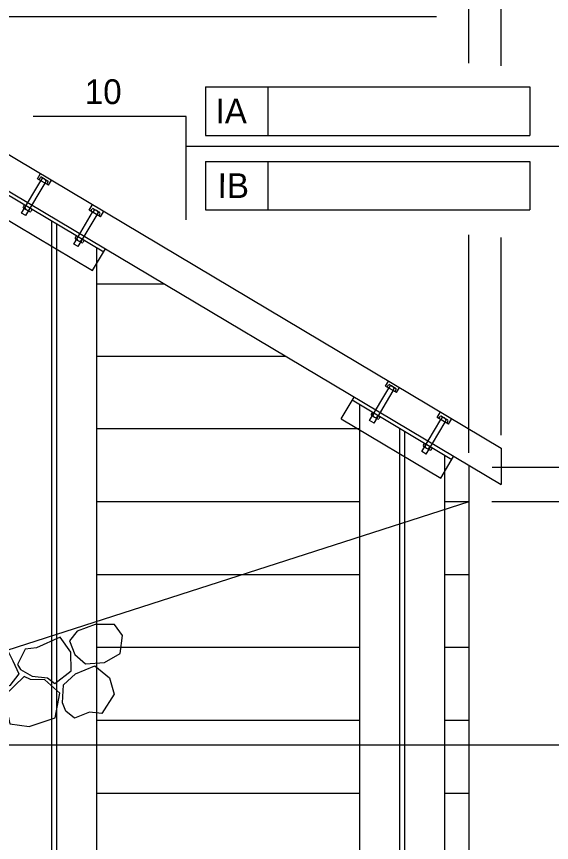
# Model space of a CAD drawing. Extents: x 638304 to 640306, y 296653 to 298435.
# Drawn here: x 639709.6 to 639774.4, y 297344.2 to 297444.4 of the extents above; entities that cross this region are included whole.
import ezdxf

# ---------------------------------------------------------------- set-up
doc = ezdxf.new("R2010")
doc.units = 0
for name, color, linetype in [('4', 7, 'Continuous'), ('Level 3', 7, 'Continuous'), ('Level 4', 7, 'Continuous'), ('Level 8', 7, 'Continuous')]:
    doc.layers.add(name, color=color, linetype=linetype)

# ---------------------------------------------------------------- blocks, each defined once
blk = doc.blocks.new('ROCK')
at = {"layer": '4'}
for points in [[(2.36725, 1.088), (2.2065, 0.82625), (2.378625, 0.506625), (2.66975, 0.3095), (3.128875, 0.403375), (3.48475, 0.6775), (3.4915, 1.123375), (3.25625, 1.36725), (2.783625, 1.308375)], [(1.10175, -0.02725), (1.4015, -0.159125), (1.78825, -0.148875), (1.980875, -0.266), (2.343375, 0.09475), (2.27875, 0.5505), (1.969375, 0.883), (1.4225, 0.553625), (1.152875, 0.479), (1.0105, 0.082)], [(0.74675, 0.359875), (0.882, 0.16), (1.072875, -0.144), (0.892, -0.457375), (0.448125, -0.758625), (0.1, -0.49325), (-0.095, -0.146375), (0.202875, 0.1025), (0.579125, 0.219875)], [(2.231375, -0.71725), (2.2025, -0.266375), (2.45475, 0.037125), (2.9085, 0.28875), (3.2995, 0.047625), (3.46875, -0.344), (3.231625, -0.855), (2.92, -0.860375), (2.5765, -1.054625), (2.340375, -0.904375)], [(1.2085, -0.192875), (0.778375, -0.737625), (1.008375, -1.391375), (1.48725, -1.396875), (2.09825, -1.106625), (2.133375, -0.486375), (1.723125, -0.203375), (1.37425, -0.239875)]]:
    blk.add_lwpolyline(points, close=True, dxfattribs=at)

msp = doc.modelspace()

# ---------------------------------------------------------------- linework, layer by layer
at = {"layer": 'Level 3'}
for p, q in [((639680.52, 297444.35), (639768.27, 297392.03)), ((639680.52, 297439.93), (639768.27, 297387.61)), ((639712.08, 297424.7), (639712.44, 297425.32)), ((639710.17, 297420.53), (639712.49, 297424.46)), ((639713.43, 297423.91), (639712.08, 297424.7)), ((639712.28, 297424.58), (639712.44, 297424.85)), ((639712.66, 297424.72), (639712.51, 297424.45)), ((639712.6, 297424.87), (639713.32, 297424.45)), ((639713.14, 297424.44), (639712.98, 297424.17)), ((639713.23, 297424.02), (639713.38, 297424.3)), ((639713.43, 297423.91), (639713.79, 297424.52)), ((639710.7, 297420.22), (639713.02, 297424.15)), ((639710.5, 297421.56), (639710.34, 297421.29)), ((639710.56, 297421.16), (639710.72, 297421.43)), ((639718.37, 297420.88), (639718.73, 297421.5)), ((639706.7, 297420.75), (639718.78, 297413.55)), ((639710.7, 297420.22), (639710.17, 297420.53)), ((639710.4, 297421.14), (639711.12, 297420.72)), ((639711.04, 297420.88), (639711.19, 297421.15)), ((639711.44, 297421.01), (639711.28, 297420.74)), ((639716.49, 297416.77), (639718.78, 297420.64)), ((639717.02, 297416.46), (639719.31, 297420.33)), ((639719.72, 297420.09), (639718.37, 297420.88)), ((639718.57, 297420.76), (639718.73, 297421.03)), ((639718.95, 297420.9), (639718.79, 297420.63)), ((639718.89, 297421.06), (639719.61, 297420.63)), ((639719.43, 297420.62), (639719.27, 297420.35)), ((639719.52, 297420.21), (639719.67, 297420.48)), ((639719.72, 297420.09), (639720.08, 297420.7)), ((639716.81, 297417.8), (639716.65, 297417.53)), ((639716.71, 297417.38), (639717.44, 297416.96)), ((639716.88, 297417.39), (639717.04, 297417.66)), ((639717.36, 297417.12), (639717.52, 297417.38)), ((639717.76, 297417.24), (639717.6, 297416.97)), ((639717.02, 297416.46), (639716.49, 297416.77)), ((639718.78, 297413.55), (639720.35, 297416.18)), ((639719.25, 297414.35), (639719.25, 297371.02)), ((639727.5, 297411.92), (639719.25, 297411.92)), ((639719.25, 297405.66), (639719.25, 297400.99)), ((639742.22, 297403.15), (639719.25, 297403.15)), ((639752.35, 297395.38), (639754.67, 297399.31)), ((639754.26, 297399.55), (639754.62, 297400.17)), ((639755.61, 297398.76), (639754.26, 297399.55)), ((639754.46, 297399.43), (639754.62, 297399.7)), ((639754.84, 297399.57), (639754.69, 297399.3)), ((639754.78, 297399.72), (639755.5, 297399.3)), ((639755.32, 297399.29), (639755.16, 297399.02)), ((639755.61, 297398.76), (639755.97, 297399.37)), ((639748.88, 297395.6), (639750.46, 297398.23)), ((639752.88, 297395.07), (639755.2, 297399)), ((639755.41, 297398.87), (639755.56, 297399.15)), ((639752.68, 297396.41), (639752.52, 297396.14)), ((639752.74, 297396.01), (639752.9, 297396.28)), ((639760.55, 297395.73), (639760.91, 297396.35)), ((639748.88, 297395.6), (639760.96, 297388.4)), ((639752.88, 297395.07), (639752.35, 297395.38)), ((639752.58, 297395.99), (639753.29, 297395.57)), ((639753.22, 297395.73), (639753.37, 297396)), ((639753.62, 297395.86), (639753.46, 297395.59)), ((639758.67, 297391.62), (639760.96, 297395.49)), ((639761.9, 297394.94), (639760.55, 297395.73)), ((639760.75, 297395.61), (639760.91, 297395.88)), ((639761.13, 297395.75), (639760.97, 297395.48)), ((639761.07, 297395.91), (639761.79, 297395.48)), ((639761.61, 297395.47), (639761.45, 297395.2)), ((639761.7, 297395.06), (639761.85, 297395.33)), ((639761.9, 297394.94), (639762.26, 297395.55)), ((639751.12, 297394.37), (639719.25, 297394.37)), ((639751.12, 297394.26), (639751.12, 297381.26)), ((639759.2, 297391.31), (639761.49, 297395.18)), ((639758.99, 297392.65), (639758.83, 297392.38)), ((639758.89, 297392.23), (639759.62, 297391.81)), ((639759.06, 297392.24), (639759.22, 297392.51)), ((639759.54, 297391.97), (639759.7, 297392.23)), ((639759.2, 297391.31), (639758.67, 297391.62)), ((639759.94, 297392.09), (639759.78, 297391.82)), ((639768.27, 297392.03), (639768.27, 297387.61)), ((639760.96, 297388.4), (639762.53, 297391.03)), ((639761.43, 297389.2), (639761.43, 297384.63)), ((639764.38, 297389.93), (639764.38, 297385.53)), ((639764.38, 297385.53), (639673.75, 297356.36)), ((639751.12, 297385.53), (639719.25, 297385.53)), ((639764.38, 297385.53), (639761.43, 297385.53)), ((639764.38, 297385.53), (639764.38, 297323.64)), ((639761.43, 297384.7), (639761.43, 297312.21)), ((639751.12, 297381.26), (639751.12, 297311.93)), ((639736.91, 297376.69), (639719.25, 297376.69)), ((639751.12, 297376.69), (639736.91, 297376.69)), ((639764.38, 297376.69), (639761.43, 297376.69)), ((639719.25, 297371.02), (639719.25, 297312.21)), ((639751.12, 297367.85), (639719.25, 297367.85)), ((639764.38, 297367.85), (639761.43, 297367.85)), ((639751.12, 297359.01), (639719.25, 297359.01)), ((639764.38, 297359.01), (639761.43, 297359.01)), ((639751.12, 297350.17), (639719.25, 297350.17)), ((639764.38, 297350.17), (639761.43, 297350.17))]:
    msp.add_line(p, q, dxfattribs=at)
for centre, radius, start, end in [((639712.53, 297424.75), 0.139, 346.8498, 131.9461), ((639712.73, 297424.29), 0.438, 20.448, 98.348), ((639713.23, 297424.32), 0.153, 61.225, 128.111), ((639713.23, 297424.32), 0.153, 350.6849, 61.225), ((639710.47, 297421.26), 0.139, 166.9183, 312.0147), ((639710.97, 297421.31), 0.438, 200.5165, 278.4165), ((639711.19, 297420.85), 0.153, 170.7534, 237.6394), ((639711.19, 297420.85), 0.153, 237.6394, 308.1795), ((639718.82, 297420.93), 0.139, 346.8498, 131.9461), ((639719.02, 297420.47), 0.438, 20.448, 98.348), ((639719.52, 297420.5), 0.153, 61.225, 128.111), ((639719.52, 297420.5), 0.153, 350.6849, 61.225), ((639716.79, 297417.49), 0.139, 166.9183, 312.0147), ((639717.29, 297417.54), 0.438, 200.5165, 278.4165), ((639717.51, 297417.09), 0.153, 170.7534, 237.6394), ((639717.51, 297417.09), 0.153, 237.6394, 308.1795), ((639754.71, 297399.6), 0.139, 346.8498, 131.9461), ((639754.91, 297399.14), 0.438, 20.448, 98.348), ((639755.41, 297399.17), 0.153, 61.225, 128.111), ((639755.41, 297399.17), 0.153, 350.6849, 61.225), ((639752.65, 297396.11), 0.139, 166.9183, 312.0147), ((639753.15, 297396.16), 0.438, 200.5165, 278.4165), ((639753.37, 297395.7), 0.153, 170.7534, 237.6394), ((639753.37, 297395.7), 0.153, 237.6394, 308.1795), ((639761, 297395.78), 0.139, 346.8498, 131.9461), ((639761.2, 297395.32), 0.438, 20.448, 98.348), ((639761.7, 297395.35), 0.153, 61.225, 128.111), ((639761.7, 297395.35), 0.153, 350.6849, 61.225), ((639758.97, 297392.34), 0.139, 166.9183, 312.0147), ((639759.47, 297392.39), 0.438, 200.5165, 278.4165), ((639759.69, 297391.94), 0.153, 170.7534, 237.6394), ((639759.69, 297391.94), 0.153, 237.6394, 308.1795)]:
    msp.add_arc(centre, radius, start, end, dxfattribs=at)
at = {"layer": 'Level 4'}
for p, q in [((639764.38, 297438.71), (639764.38, 297451.07)), ((639768.27, 297438.38), (639768.27, 297450.75)), ((639697.37, 297444.35), (639760.46, 297444.35)), ((639732.47, 297435.85), (639771.77, 297435.85)), ((639732.47, 297435.85), (639732.47, 297429.95)), ((639740.02, 297435.85), (639740.02, 297429.95)), ((639771.77, 297435.85), (639771.77, 297429.95)), ((639730.13, 297432.24), (639711.58, 297432.24)), ((639730.13, 297419.73), (639730.13, 297432.24)), ((639732.47, 297429.95), (639771.77, 297429.95)), ((639804.83, 297428.6), (639730.13, 297428.6)), ((639732.47, 297426.8), (639771.77, 297426.8)), ((639732.47, 297426.8), (639732.47, 297420.91)), ((639740.02, 297426.8), (639740.02, 297420.91)), ((639771.77, 297426.8), (639771.77, 297420.91)), ((639732.47, 297420.91), (639771.77, 297420.91)), ((639764.38, 297391.46), (639764.38, 297417.88)), ((639768.27, 297393.61), (639768.27, 297417.55)), ((639767.2, 297389.71), (639868.46, 297389.71)), ((639775.41, 297385.53), (639767.14, 297385.53)), ((639775.41, 297356.01), (639680.01, 297356.01))]:
    msp.add_line(p, q, dxfattribs=at)
at = {"layer": 'Level 8'}
for p, q in [((639708.06, 297423.02), (639720.13, 297415.82)), ((639713.8, 297419.6), (639713.8, 297311.91)), ((639714.39, 297419.24), (639714.39, 297311.54)), ((639719.25, 297416.35), (639719.25, 297414.35)), ((639750.24, 297397.87), (639762.31, 297390.67)), ((639751.12, 297397.34), (639751.12, 297394.26)), ((639755.98, 297394.45), (639755.98, 297311.91)), ((639756.57, 297394.09), (639756.57, 297311.54)), ((639761.43, 297391.2), (639761.43, 297389.2))]:
    msp.add_line(p, q, dxfattribs=at)

# ---------------------------------------------------------------- block references
at = {"layer": 'Level 4', "xscale": 4.911876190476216, "yscale": 4.911876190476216, "rotation": -7.30063298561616}
msp.add_blockref('ROCK', (639704.7, 297366.03), dxfattribs=at)

# ---------------------------------------------------------------- texts
at = {"layer": 'Level 4'}
msp.add_text('10', height=3, dxfattribs=at).set_placement((639717.83, 297433.75))
for s, p in [('IA', (639733.68, 297431.4)), ('IB', (639733.93, 297422.36))]:
    msp.add_text(s, height=3, rotation=359.9382, dxfattribs=at).set_placement(p)

doc.saveas('drawing.dxf')
